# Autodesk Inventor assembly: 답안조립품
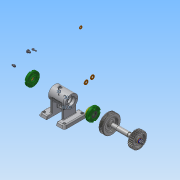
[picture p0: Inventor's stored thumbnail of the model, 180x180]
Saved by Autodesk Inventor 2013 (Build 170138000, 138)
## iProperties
Created: 2008-12
Part Number: 답안조립품
Document SubType Name: Assembly
Designer: Administrator
Author: Administrator
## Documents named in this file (16)
- C:\Users\Administrator\Desktop\460708V1011\답안조립품.iam
- C:\Users\Administrator\Desktop\460708V1011\본체.ipt
- C:\Users\Administrator\Desktop\460708V1011\V벨트풀리.ipt
- C:\Users\Administrator\Desktop\460708V1011\너트 M 8.ipt
- C:\Users\Administrator\Desktop\460708V1011\니플 M 6 x 0.75.ipt
- C:\Users\Administrator\Desktop\460708V1011\베어링 15 x 32 x 9.ipt
- C:\Users\Administrator\Desktop\460708V1011\볼트 M 6 x 8.ipt
- C:\Users\Administrator\Desktop\460708V1011\볼트 M4 x 12.ipt
- C:\Users\Administrator\Desktop\460708V1011\스퍼기어.ipt
- C:\Users\Administrator\Desktop\460708V1011\스프링와셔 8.ipt
- C:\Users\Administrator\Desktop\460708V1011\오일 실 15 25 7.ipt
- C:\Users\Administrator\Desktop\460708V1011\와셔 6x11.5.ipt
- C:\Users\Administrator\Desktop\460708V1011\와셔 8x17.ipt
- C:\Users\Administrator\Desktop\460708V1011\축.ipt
- C:\Users\Administrator\Desktop\460708V1011\커버.ipt
- C:\Users\Administrator\Desktop\460708V1011\키 3 x 3 x 12.ipt
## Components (4 placed, 3 different names)
1. V벨트풀리:1
2. KS B 2023 6002 - 15 x 32 x 9:1
3. ISO 4762 M4 x 12:1
4. KS B 2023 6002 - 15 x 32 x 9:2
